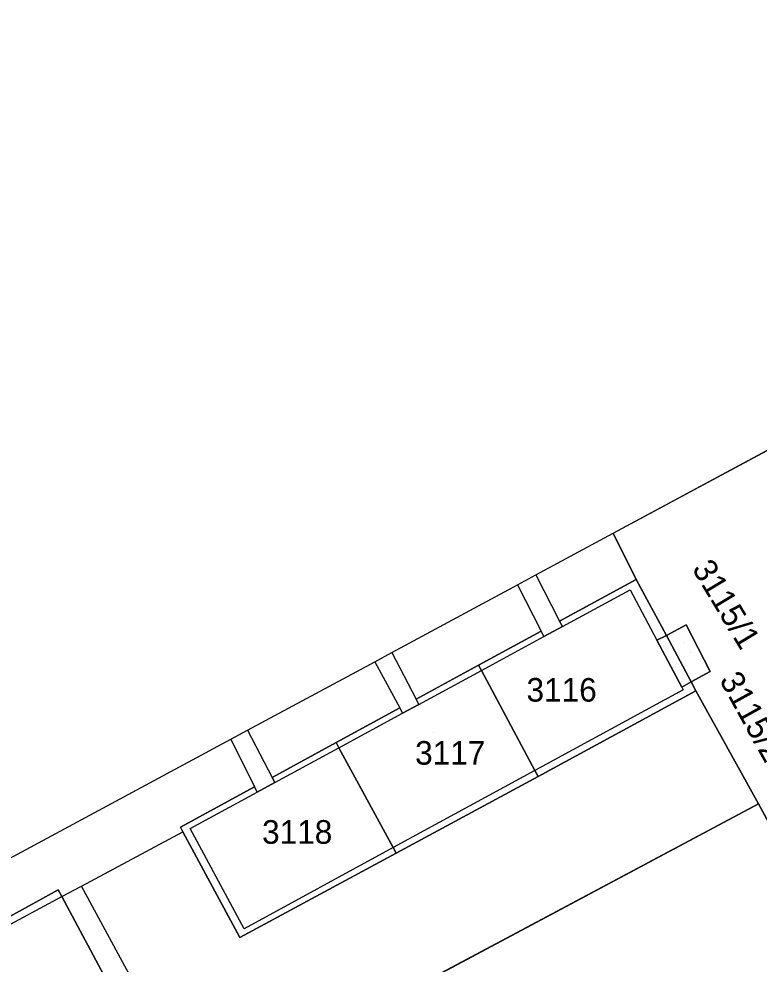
# Model space of a CAD drawing. Extents: x -264070 to -262271, y -1238894 to -1238141.
# Drawn here: x -263238.5 to -263175.7, y -1238393.6 to -1238313.6 of the extents above; entities that cross this region are included whole.
import ezdxf

# ---------------------------------------------------------------- set-up
doc = ezdxf.new("R2010")
doc.units = 0
for name, color, linetype in [('body_kn', 7, 'Continuous'), ('katuz_linie', 7, 'Continuous'), ('kladpar_druhypozemkov', 7, 'Continuous'), ('kladpar_hranice', 7, 'Continuous'), ('kladpar_parcelnecisla', 7, 'Continuous'), ('kladpar_plochy', 7, 'Continuous'), ('kladpar_sipky', 7, 'Continuous'), ('zappar_hrandruhpozemk', 7, 'Continuous'), ('zuob_linie', 7, 'Continuous'), ('zuob_plochy', 7, 'Continuous')]:
    doc.layers.add(name, color=color, linetype=linetype)

msp = doc.modelspace()

# ---------------------------------------------------------------- linework, layer by layer
at = {"layer": 'body_kn'}
for p, q in [((-263188.09, -1238357.15), (-263188.09, -1238357.15)), ((-263194.64, -1238360.68), (-263194.64, -1238360.68)), ((-263194.64, -1238360.68), (-263194.64, -1238360.68)), ((-263186.15, -1238361.06), (-263186.15, -1238361.06)), ((-263186.15, -1238361.06), (-263186.15, -1238361.06)), ((-263196.19, -1238361.51), (-263196.19, -1238361.51)), ((-263196.19, -1238361.51), (-263196.19, -1238361.51)), ((-263186.64, -1238361.93), (-263186.64, -1238361.93)), ((-263192.63, -1238364.58), (-263192.63, -1238364.58)), ((-263194.2, -1238365.45), (-263194.2, -1238365.45)), ((-263192.38, -1238365.04), (-263192.38, -1238365.04)), ((-263192.38, -1238365.04), (-263192.38, -1238365.04)), ((-263181.91, -1238364.9), (-263181.91, -1238364.9)), ((-263181.91, -1238364.9), (-263181.91, -1238364.9)), ((-263193.97, -1238365.9), (-263193.97, -1238365.9)), ((-263184.4, -1238366.2), (-263184.4, -1238366.2)), ((-263183.58, -1238365.81), (-263183.58, -1238365.81)), ((-263183.58, -1238365.81), (-263183.58, -1238365.81)), ((-263206.85, -1238367.25), (-263206.85, -1238367.25)), ((-263206.85, -1238367.25), (-263206.85, -1238367.25)), ((-263208.3, -1238368.03), (-263208.3, -1238368.03)), ((-263208.3, -1238368.03), (-263208.3, -1238368.03)), ((-263199.5, -1238368.32), (-263199.5, -1238368.32)), ((-263199.5, -1238368.32), (-263199.5, -1238368.32)), ((-263199.26, -1238368.76), (-263199.26, -1238368.76)), ((-263199.26, -1238368.76), (-263199.26, -1238368.76)), ((-263179.88, -1238368.86), (-263179.88, -1238368.86)), ((-263182.28, -1238370.19), (-263182.28, -1238370.19)), ((-263182.28, -1238370.19), (-263182.28, -1238370.19)), ((-263181.49, -1238369.74), (-263181.49, -1238369.74)), ((-263181.49, -1238369.74), (-263181.49, -1238369.74)), ((-263182.16, -1238370.42), (-263182.16, -1238370.42)), ((-263181.07, -1238370.5), (-263181.07, -1238370.5)), ((-263204.8, -1238371.19), (-263204.8, -1238371.19)), ((-263204.55, -1238371.64), (-263204.55, -1238371.64)), ((-263204.55, -1238371.64), (-263204.55, -1238371.64)), ((-263206.18, -1238371.94), (-263206.18, -1238371.94)), ((-263205.94, -1238372.4), (-263205.94, -1238372.4)), ((-263219.08, -1238373.84), (-263219.08, -1238373.84)), ((-263219.08, -1238373.84), (-263219.08, -1238373.84)), ((-263220.5, -1238374.6), (-263220.5, -1238374.6)), ((-263220.5, -1238374.6), (-263220.5, -1238374.6)), ((-263211.58, -1238374.88), (-263211.58, -1238374.88)), ((-263211.58, -1238374.88), (-263211.58, -1238374.88)), ((-263211.33, -1238375.31), (-263211.33, -1238375.31)), ((-263211.33, -1238375.31), (-263211.33, -1238375.31)), ((-263194.72, -1238377.25), (-263194.72, -1238377.25)), ((-263194.72, -1238377.25), (-263194.72, -1238377.25)), ((-263217, -1238377.83), (-263217, -1238377.83)), ((-263216.78, -1238378.27), (-263216.78, -1238378.27)), ((-263216.78, -1238378.27), (-263216.78, -1238378.27)), ((-263194.46, -1238377.74), (-263194.46, -1238377.74)), ((-263218.48, -1238378.64), (-263218.48, -1238378.64)), ((-263218.26, -1238379.07), (-263218.26, -1238379.07)), ((-263175.78, -1238380.08), (-263175.78, -1238380.08)), ((-263175.78, -1238380.08), (-263175.78, -1238380.08)), ((-263224.77, -1238382.05), (-263224.77, -1238382.05)), ((-263223.94, -1238382.15), (-263223.94, -1238382.15)), ((-263224.56, -1238382.44), (-263224.56, -1238382.44)), ((-263206.73, -1238383.77), (-263206.73, -1238383.77)), ((-263206.73, -1238383.77), (-263206.73, -1238383.77)), ((-263206.48, -1238384.24), (-263206.48, -1238384.24)), ((-263233.16, -1238387.03), (-263233.16, -1238387.03)), ((-263233.16, -1238387.03), (-263233.16, -1238387.03)), ((-263235.14, -1238387.34), (-263235.14, -1238387.34)), ((-263234.83, -1238387.93), (-263234.83, -1238387.93)), ((-263234.83, -1238387.93), (-263234.83, -1238387.93)), ((-263219.37, -1238390.65), (-263219.37, -1238390.65)), ((-263219.72, -1238391.39), (-263219.72, -1238391.39))]:
    msp.add_line(p, q, dxfattribs=at)
at = {"layer": 'katuz_linie'}
msp.add_lwpolyline([(-263246.2, -1238388.44), (-263220.5, -1238374.6), (-263219.08, -1238373.84), (-263208.3, -1238368.03), (-263206.85, -1238367.25), (-263196.19, -1238361.51), (-263194.64, -1238360.68), (-263188.09, -1238357.15), (-263164.06, -1238344.21), (-263162.21, -1238343.23), (-263156.91, -1238340.42), (-263154.99, -1238339.4), (-263153.35, -1238338.53), (-263133.32, -1238327.67), (-263107.05, -1238313.57)], dxfattribs=at)
at = {"layer": 'kladpar_druhypozemkov'}
for p, q in [((-263181.55, -1238367.27), (-263181.55, -1238367.27)), ((-263182.68, -1238368.22), (-263182.68, -1238368.22)), ((-263192.75, -1238369.43), (-263192.75, -1238369.43)), ((-263203.28, -1238374), (-263203.28, -1238374)), ((-263215.63, -1238381.35), (-263215.63, -1238381.35))]:
    msp.add_line(p, q, dxfattribs=at)
at = {"layer": 'kladpar_hranice'}
for p, q in [((-263183.58, -1238365.81), (-263181.91, -1238364.9)), ((-263183.58, -1238365.81), (-263181.49, -1238369.74)), ((-263181.49, -1238369.74), (-263183.58, -1238365.81)), ((-263212.5, -1238399.65), (-263175.78, -1238380.08))]:
    msp.add_line(p, q, dxfattribs=at)
for points in [[(-263162.72, -1238404.1), (-263175.78, -1238380.08), (-263181.07, -1238370.5), (-263181.49, -1238369.74), (-263179.88, -1238368.86), (-263181.91, -1238364.9), (-263183.58, -1238365.81), (-263186.15, -1238361.06), (-263188.09, -1238357.15), (-263164.06, -1238344.21), (-263158.78, -1238354.03), (-263157.81, -1238355.82), (-263152.15, -1238366.34), (-263151.26, -1238367.98), (-263145.58, -1238378.53), (-263144.81, -1238379.96)], [(-263246.2, -1238388.44), (-263220.5, -1238374.6), (-263219.08, -1238373.84), (-263208.3, -1238368.03), (-263206.85, -1238367.25), (-263196.19, -1238361.51), (-263194.64, -1238360.68), (-263188.09, -1238357.15), (-263186.15, -1238361.06), (-263192.63, -1238364.58), (-263192.38, -1238365.04), (-263193.97, -1238365.9), (-263194.2, -1238365.45), (-263199.5, -1238368.32), (-263204.8, -1238371.19), (-263204.55, -1238371.64), (-263205.94, -1238372.4), (-263206.18, -1238371.94), (-263211.58, -1238374.88), (-263217, -1238377.83), (-263216.78, -1238378.27), (-263218.26, -1238379.07), (-263218.48, -1238378.64), (-263224.77, -1238382.05), (-263224.56, -1238382.44), (-263219.72, -1238391.39), (-263206.48, -1238384.24), (-263194.46, -1238377.74), (-263181.07, -1238370.5), (-263175.78, -1238380.08), (-263212.5, -1238399.65)], [(-263186.15, -1238361.06), (-263183.58, -1238365.81), (-263184.4, -1238366.2), (-263182.28, -1238370.19), (-263181.49, -1238369.74), (-263181.07, -1238370.5), (-263194.46, -1238377.74), (-263194.72, -1238377.25), (-263199.26, -1238368.76), (-263199.5, -1238368.32), (-263194.2, -1238365.45), (-263193.97, -1238365.9), (-263192.38, -1238365.04), (-263192.63, -1238364.58), (-263186.15, -1238361.06)], [(-263181.91, -1238364.9), (-263179.88, -1238368.86), (-263181.49, -1238369.74)], [(-263181.49, -1238369.74), (-263182.28, -1238370.19), (-263184.4, -1238366.2), (-263183.58, -1238365.81)], [(-263199.5, -1238368.32), (-263199.26, -1238368.76), (-263194.72, -1238377.25), (-263194.46, -1238377.74), (-263206.48, -1238384.24), (-263206.73, -1238383.77), (-263211.33, -1238375.31), (-263211.58, -1238374.88), (-263206.18, -1238371.94), (-263205.94, -1238372.4), (-263204.55, -1238371.64), (-263204.8, -1238371.19), (-263199.5, -1238368.32)], [(-263211.58, -1238374.88), (-263211.33, -1238375.31), (-263206.73, -1238383.77), (-263206.48, -1238384.24), (-263219.72, -1238391.39), (-263224.56, -1238382.44), (-263224.77, -1238382.05), (-263218.48, -1238378.64), (-263218.26, -1238379.07), (-263216.78, -1238378.27), (-263217, -1238377.83), (-263211.58, -1238374.88)], [(-263175.78, -1238380.08), (-263162.72, -1238404.1), (-263172.77, -1238423.15), (-263194.88, -1238434.15), (-263212.5, -1238399.65)], [(-263172.77, -1238423.15), (-263162.72, -1238404.1), (-263141.74, -1238442.69), (-263197.46, -1238469.33), (-263205.85, -1238453.87), (-263204.16, -1238452.86), (-263205.04, -1238451.28), (-263206.77, -1238452.24), (-263215.03, -1238436.74), (-263218.75, -1238438.85), (-263223.35, -1238429.83), (-263214.85, -1238425.23), (-263221.53, -1238412.75), (-263228.19, -1238400.33), (-263234.83, -1238387.93), (-263235.14, -1238387.34), (-263244.18, -1238392.32)], [(-263234.83, -1238387.93), (-263228.19, -1238400.33), (-263236.84, -1238404.98), (-263237.25, -1238405.19), (-263244.18, -1238392.32), (-263235.14, -1238387.34), (-263234.83, -1238387.93)]]:
    msp.add_lwpolyline(points, dxfattribs=at)
at = {"layer": 'kladpar_plochy'}
for p, q in [((-263188.09, -1238357.15), (-263164.06, -1238344.21)), ((-263186.15, -1238361.06), (-263188.09, -1238357.15)), ((-263183.58, -1238365.81), (-263186.15, -1238361.06)), ((-263181.91, -1238364.9), (-263183.58, -1238365.81)), ((-263179.88, -1238368.86), (-263181.91, -1238364.9)), ((-263181.49, -1238369.74), (-263179.88, -1238368.86)), ((-263181.07, -1238370.5), (-263181.49, -1238369.74)), ((-263175.78, -1238380.08), (-263181.07, -1238370.5)), ((-263212.5, -1238399.65), (-263175.78, -1238380.08)), ((-263175.78, -1238380.08), (-263162.72, -1238404.1)), ((-263162.72, -1238404.1), (-263175.78, -1238380.08))]:
    msp.add_line(p, q, dxfattribs=at)
for points in [[(-263246.2, -1238388.44), (-263220.5, -1238374.6), (-263219.08, -1238373.84), (-263208.3, -1238368.03), (-263206.85, -1238367.25), (-263196.19, -1238361.51), (-263194.64, -1238360.68), (-263188.09, -1238357.15), (-263186.15, -1238361.06), (-263192.63, -1238364.58), (-263192.38, -1238365.04), (-263193.97, -1238365.9), (-263194.2, -1238365.45), (-263199.5, -1238368.32), (-263204.8, -1238371.19), (-263204.55, -1238371.64), (-263205.94, -1238372.4), (-263206.18, -1238371.94), (-263211.58, -1238374.88), (-263217, -1238377.83), (-263216.78, -1238378.27), (-263218.26, -1238379.07), (-263218.48, -1238378.64), (-263224.77, -1238382.05), (-263224.56, -1238382.44), (-263219.72, -1238391.39), (-263206.48, -1238384.24), (-263194.46, -1238377.74), (-263181.07, -1238370.5), (-263175.78, -1238380.08), (-263212.5, -1238399.65)], [(-263228.19, -1238400.33), (-263234.83, -1238387.93), (-263235.14, -1238387.34), (-263244.18, -1238392.32)]]:
    msp.add_lwpolyline(points, dxfattribs=at)
for points in [[(-263186.15, -1238361.06), (-263183.58, -1238365.81), (-263184.4, -1238366.2), (-263182.28, -1238370.19), (-263181.49, -1238369.74), (-263181.07, -1238370.5), (-263194.46, -1238377.74), (-263194.72, -1238377.25), (-263199.26, -1238368.76), (-263199.5, -1238368.32), (-263194.2, -1238365.45), (-263193.97, -1238365.9), (-263192.38, -1238365.04), (-263192.63, -1238364.58)], [(-263181.91, -1238364.9), (-263179.88, -1238368.86), (-263181.49, -1238369.74), (-263183.58, -1238365.81)], [(-263181.49, -1238369.74), (-263182.28, -1238370.19), (-263184.4, -1238366.2), (-263183.58, -1238365.81)], [(-263199.5, -1238368.32), (-263199.26, -1238368.76), (-263194.72, -1238377.25), (-263194.46, -1238377.74), (-263206.48, -1238384.24), (-263206.73, -1238383.77), (-263211.33, -1238375.31), (-263211.58, -1238374.88), (-263206.18, -1238371.94), (-263205.94, -1238372.4), (-263204.55, -1238371.64), (-263204.8, -1238371.19)], [(-263211.58, -1238374.88), (-263211.33, -1238375.31), (-263206.73, -1238383.77), (-263206.48, -1238384.24), (-263219.72, -1238391.39), (-263224.56, -1238382.44), (-263224.77, -1238382.05), (-263218.48, -1238378.64), (-263218.26, -1238379.07), (-263216.78, -1238378.27), (-263217, -1238377.83)], [(-263234.83, -1238387.93), (-263228.19, -1238400.33), (-263236.84, -1238404.98), (-263237.25, -1238405.19), (-263244.18, -1238392.32), (-263235.14, -1238387.34)]]:
    msp.add_lwpolyline(points, close=True, dxfattribs=at)
at = {"layer": 'kladpar_sipky'}
for p, q in [((-263182.04, -1238366.36), (-263182.04, -1238366.36)), ((-263182.27, -1238369.71), (-263182.27, -1238369.71))]:
    msp.add_line(p, q, dxfattribs=at)
at = {"layer": 'zappar_hrandruhpozemk'}
for p, q in [((-263194.64, -1238360.68), (-263192.63, -1238364.58)), ((-263196.19, -1238361.51), (-263194.2, -1238365.45)), ((-263192.38, -1238365.04), (-263186.64, -1238361.93)), ((-263186.64, -1238361.93), (-263184.4, -1238366.2)), ((-263199.26, -1238368.76), (-263193.97, -1238365.9)), ((-263206.85, -1238367.25), (-263204.8, -1238371.19)), ((-263208.3, -1238368.03), (-263206.18, -1238371.94)), ((-263204.55, -1238371.64), (-263199.26, -1238368.76)), ((-263182.28, -1238370.19), (-263182.16, -1238370.42)), ((-263182.16, -1238370.42), (-263194.72, -1238377.25)), ((-263211.33, -1238375.31), (-263205.94, -1238372.4)), ((-263219.08, -1238373.84), (-263217, -1238377.83)), ((-263220.5, -1238374.6), (-263218.48, -1238378.64)), ((-263216.78, -1238378.27), (-263211.33, -1238375.31)), ((-263194.72, -1238377.25), (-263206.73, -1238383.77)), ((-263223.94, -1238382.15), (-263218.26, -1238379.07)), ((-263219.37, -1238390.65), (-263223.94, -1238382.15)), ((-263233.16, -1238387.03), (-263224.56, -1238382.44)), ((-263206.73, -1238383.77), (-263219.37, -1238390.65)), ((-263234.83, -1238387.93), (-263233.16, -1238387.03)), ((-263212.95, -1238424.2), (-263233.16, -1238387.03)), ((-263243.57, -1238392.62), (-263234.83, -1238387.93))]:
    msp.add_line(p, q, dxfattribs=at)
at = {"layer": 'zuob_linie'}
msp.add_lwpolyline([(-263246.2, -1238388.44), (-263220.5, -1238374.6), (-263219.08, -1238373.84), (-263208.3, -1238368.03), (-263206.85, -1238367.25), (-263196.19, -1238361.51), (-263194.64, -1238360.68), (-263188.09, -1238357.15), (-263164.06, -1238344.21), (-263162.21, -1238343.23), (-263156.91, -1238340.42), (-263154.99, -1238339.4), (-263153.35, -1238338.53), (-263133.32, -1238327.67), (-263107.05, -1238313.57)], dxfattribs=at)
at = {"layer": 'zuob_plochy'}
msp.add_lwpolyline([(-263246.2, -1238388.44), (-263220.5, -1238374.6), (-263219.08, -1238373.84), (-263208.3, -1238368.03), (-263206.85, -1238367.25), (-263196.19, -1238361.51), (-263194.64, -1238360.68), (-263188.09, -1238357.15), (-263164.06, -1238344.21), (-263162.21, -1238343.23), (-263156.91, -1238340.42), (-263154.99, -1238339.4), (-263153.35, -1238338.53), (-263133.32, -1238327.67), (-263107.05, -1238313.57)], dxfattribs=at)

# ---------------------------------------------------------------- texts
at = {"layer": 'kladpar_parcelnecisla'}
for s, rotation, p in [('3115/1', 301, (-263181.454, -1238360.146)), ('3115/2', 299, (-263179.127, -1238369.576))]:
    msp.add_text(s, height=2, rotation=rotation, dxfattribs=at).set_placement(p)
for s, p in [('3116', (-263195.433, -1238371.41)), ('3117', (-263204.876, -1238376.75)), ('3118', (-263217.847, -1238383.45))]:
    msp.add_text(s, height=2, dxfattribs=at).set_placement(p)

doc.saveas('drawing.dxf')
